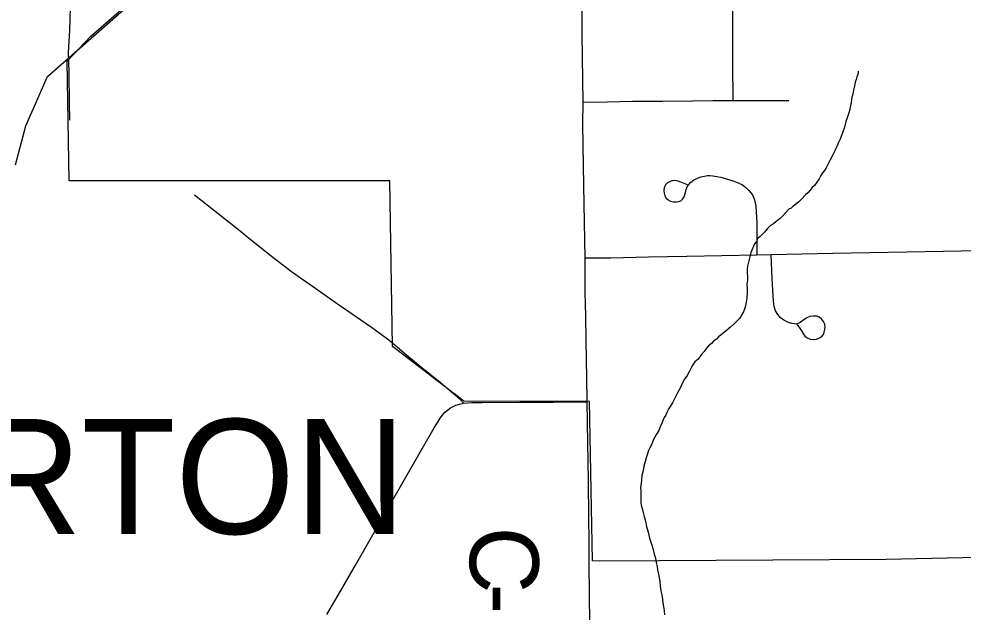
# Model space of a CAD drawing. Extents: x 103424 to 290657, y 38711 to 110967.
# Drawn here: x 156701 to 160839, y 57927 to 60525 of the extents above; entities that cross this region are included whole.
import ezdxf

# ---------------------------------------------------------------- set-up
doc = ezdxf.new("R2010")
doc.units = 0
for name, color, linetype in [('GM_X_City_Street', 7, 'Continuous'), ('GM_X_Corporation', 7, 'Continuous'), ('GM_X_Corporation_Text', 7, 'Continuous'), ('GM_X_County_Road', 7, 'Continuous'), ('GM_X_County_Road_Text', 7, 'Continuous'), ('GM_X_Minor_River', 7, 'Continuous'), ('GM_X_Rail_Line', 7, 'Continuous'), ('GM_X_Township_Road', 7, 'Continuous')]:
    doc.layers.add(name, color=color, linetype=linetype)

msp = doc.modelspace()

# ---------------------------------------------------------------- linework, layer by layer
at = {"layer": 'GM_X_City_Street'}
for points in [[(159182.5, 59478.1), (159178.7, 59713.4), (159176, 59881.9), (159173.1, 60063.8), (159173.8, 60160), (159169.7, 60457), (159169.7, 60880.9)], [(159831.2, 60168.2), (159830.6, 60333.3), (159830, 60498.3), (159829.3, 60663.4), (159828.9, 60773.7), (159828.5, 60884)], [(159173.8, 60160), (159281.4, 60162), (159391.2, 60165), (159522, 60165.6), (159652.8, 60166.2), (159742, 60167.2), (159831.2, 60168.2), (159963, 60167.3), (160076.3, 60168.2)], [(159631, 59798), (159602, 59810.6), (159590.5, 59814.7), (159576.3, 59816.9), (159564.7, 59816.2), (159555.1, 59813.6), (159544.3, 59806.9), (159535.7, 59798), (159529.8, 59787.2), (159527.9, 59774.1), (159529.8, 59761.8), (159532.7, 59751), (159538.3, 59740.6), (159546.5, 59732.8), (159557.7, 59726.8), (159570, 59724.2), (159583.4, 59723.9), (159593.4, 59725.7), (159602.4, 59728.7), (159609.8, 59735.4), (159615, 59742.8), (159619.1, 59751.8), (159622.5, 59764.8), (159625.1, 59777.9), (159629.6, 59790.1), (159637, 59800.6), (159645.9, 59810.1), (159657.5, 59818.4), (159672.8, 59825.9), (159690.7, 59833), (159705.9, 59837.1), (159718.6, 59838.9), (159729, 59839.7), (159742.3, 59838.3), (159776.9, 59832.1), (159831.1, 59815.8), (159853.4, 59807), (159872.6, 59797.9), (159887.7, 59786.8), (159900.6, 59773.9), (159915.8, 59754.1), (159925.8, 59732.1), (159930.7, 59705.8), (159933.1, 59678.2), (159934.8, 59635.7), (159935.9, 59492.2)], [(159182.5, 59478.1), (159295.2, 59479.4), (159460.2, 59483), (159544.6, 59484.9), (159629.1, 59486.7), (159782.5, 59489.5), (159935.9, 59492.2), (159997.9, 59492.9), (160132.9, 59496.2), (160267.9, 59499.6), (160430.5, 59502.7), (160593.2, 59505.7), (160751.8, 59508.6), (160910.5, 59511.5), (161075.5, 59514.2), (161212.7, 59516.4), (161349.9, 59518.6), (161514.9, 59521.3), (161649.9, 59523.5), (161736.1, 59524.9), (161784.8, 59525.7)], [(159191.8, 58847.5), (159190.8, 58952.1), (159187.6, 59117.2), (159185.6, 59223), (159183.5, 59328.9), (159182.5, 59478.1)], [(160112.4, 59186.3), (160131.4, 59158.8), (160145.5, 59135.9), (160156.3, 59127.8), (160168.7, 59122), (160182.8, 59120.4), (160197.1, 59122), (160207.7, 59126.3), (160218.5, 59132.7), (160227.1, 59143.1), (160230.9, 59152.5), (160233.4, 59164.3), (160234.3, 59175), (160232.7, 59187.8), (160227.8, 59200.1), (160219.3, 59210.9), (160209.1, 59218.7), (160196.9, 59222.8), (160182.6, 59224), (160168.2, 59221.7), (160154.5, 59215.7), (160135.4, 59202.7), (160125, 59195.2), (160116.8, 59191.2), (160109.8, 59188.9), (160088.9, 59190.8), (160074, 59195.6), (160054.1, 59205.4), (160039.6, 59216.7), (160027, 59230.6), (160017.1, 59246.5), (160011.1, 59265.7), (160007.8, 59288.9), (160002.5, 59386.9), (159997.9, 59492.9)]]:
    msp.add_lwpolyline(points, dxfattribs=at)
at = {"layer": 'GM_X_Corporation'}
msp.add_lwpolyline([(161771.2, 58184.7), (160501.7, 58157), (159508.2, 58151.7), (159244.9, 58150.4), (159215, 58151.6), (159202.5, 58850.2), (158651.2, 58850.7), (158338.2, 59090.8), (158326.5, 59816.1), (156921.7, 59816.4), (156912.5, 60339.8), (157016.4, 60449), (157152.1, 60568.5)], dxfattribs=at)
at = {"layer": 'GM_X_County_Road'}
for points in [[(159201.1, 58147.4), (159200.4, 58242.8), (159199.6, 58338.1), (159197.1, 58503.1), (159194.5, 58668.2), (159193.2, 58757.8), (159191.8, 58847.5)], [(159203.9, 57889.6), (159202.6, 57994.4), (159201.1, 58147.4)]]:
    msp.add_lwpolyline(points, dxfattribs=at)
at = {"layer": 'GM_X_Minor_River'}
for points in [[(160379.8, 60296.4), (160380, 60286.3), (160374.2, 60272), (160370.5, 60259.9), (160366.7, 60247.7), (160363, 60231.4), (160359.3, 60213.2), (160355.7, 60194.9), (160351.9, 60182.7), (160350.1, 60170.6), (160348.4, 60158.4), (160344.7, 60138.1), (160341.1, 60121.9), (160335.3, 60105.6), (160331.6, 60091.4), (160325.9, 60075.2), (160322.1, 60060.9), (160318.4, 60046.7), (160312.7, 60030.4), (160307, 60014.2), (160301.3, 59997.9), (160293.5, 59983.6), (160287.7, 59969.3), (160281.9, 59957.1), (160276.1, 59944.8), (160268.3, 59930.5), (160256.7, 59908.1), (160247, 59887.7), (160239.2, 59873.4), (160231.4, 59861.1), (160223.5, 59850.8), (160213.7, 59836.5), (160207.9, 59824.2), (160198.1, 59809.9), (160188.3, 59795.5), (160176.4, 59785.2), (160168.6, 59774.9), (160160.7, 59764.7), (160148.8, 59754.3), (160131, 59735.8), (160119.1, 59723.4), (160105.2, 59713), (160095.3, 59704.7), (160085.3, 59696.4), (160075.3, 59692.1), (160061.5, 59675.7), (160049.7, 59663.3), (160035.8, 59648.9), (160019.9, 59638.5), (160008, 59628.1), (159996, 59619.8), (159982.1, 59607.3), (159968.3, 59590.9), (159958.5, 59580.6), (159948.6, 59570.3), (159938.6, 59564), (159934.8, 59551.8), (159925, 59539.5), (159909.6, 59502.8), (159904, 59482.5), (159898.4, 59460.1), (159894.7, 59441.9), (159893, 59427.7), (159894, 59381.3), (159892.3, 59363.1), (159892.7, 59344.9), (159893.1, 59326.8), (159891.6, 59302.5), (159888, 59284.3), (159886.3, 59268.1), (159882.5, 59257.9), (159876.8, 59241.6), (159867, 59225.3), (159859.2, 59213), (159845.3, 59198.5), (159833.5, 59186.2), (159819.5, 59175.8), (159801.7, 59159.2), (159787.8, 59148.8), (159777.8, 59140.5), (159767.9, 59132.2), (159758, 59121.9), (159746.1, 59113.6), (159736.2, 59103.3), (159724.3, 59092.9), (159714.4, 59082.6), (159704.6, 59068.3), (159690.8, 59053.8), (159679, 59035.4), (159663.1, 59023), (159655.3, 59010.7), (159647.5, 58996.4), (159639.7, 58982.1), (159630, 58963.7), (159618.2, 58947.3), (159608.5, 58928.9), (159598.9, 58908.5), (159587.2, 58888.1), (159577.5, 58867.7), (159565.9, 58843.2), (159550.3, 58818.6)], [(159550.3, 58818.6), (159542.5, 58804.3), (159536.7, 58790.1), (159528.9, 58779.8), (159525, 58769.6), (159521.2, 58757.4), (159513.5, 58741.1), (159505.8, 58722.7), (159496.1, 58706.4), (159490.2, 58696.2), (159484.4, 58685.9), (159472.8, 58657.4), (159467, 58647.2), (159461.2, 58635), (159455.5, 58616.7), (159449.8, 58602.4), (159446.1, 58586.2), (159440.4, 58565.9), (159436.8, 58547.6), (159431.2, 58525.3), (159429.6, 58507.1), (159427.9, 58490.9), (159426.2, 58474.7), (159426.6, 58456.5), (159426.9, 58440.4), (159427.3, 58422.2), (159427.7, 58406.1), (159430, 58390), (159434.4, 58375.9), (159436.7, 58363.9), (159441.1, 58345.8), (159447.6, 58325.8), (159452.1, 58301.6), (159458.7, 58277.5), (159465.3, 58251.4), (159474, 58225.4), (159480.5, 58201.3), (159485, 58181.2), (159491.5, 58163.2), (159493.9, 58145), (159498.3, 58127), (159500.7, 58110.9), (159505.1, 58092.8), (159507.5, 58076.7), (159509.8, 58060.6), (159512.3, 58040.5), (159514.7, 58020.3), (159519.1, 58002.2), (159521.5, 57984.1), (159523.9, 57968), (159526.3, 57951.9), (159528.7, 57933.8), (159531.1, 57915.7)]]:
    msp.add_lwpolyline(points, dxfattribs=at)
at = {"layer": 'GM_X_Rail_Line'}
msp.add_lwpolyline([(156685.9, 59886.4), (156731.6, 60056.7), (156827.1, 60272.6), (158961.1, 62145.8), (159164.6, 62415.7), (159376.3, 62752.1), (159604.7, 63009.7), (159911.9, 63184.1), (160152.8, 63238.1), (160415.4, 63267.2), (161709.6, 63308.7)], dxfattribs=at)
at = {"layer": 'GM_X_Township_Road'}
for points in [[(156919.9, 60337.6), (156918.6, 60376.3), (156924.7, 60475.5), (156927.7, 60574.4), (156921.6, 60725.4), (156914, 60842.5)], [(156925, 60081.5), (156923.5, 60155.5), (156921.6, 60287.9), (156919.9, 60337.6)], [(157699.1, 59572.6), (157678.3, 59589.2), (157574.7, 59671.5), (157471.2, 59753.9)], [(158098.4, 59276.4), (158003.4, 59342.7), (157895.4, 59417.9), (157807.4, 59486.4), (157699.1, 59572.6)], [(158339, 59105), (158317.4, 59122.3), (158246.8, 59173.1), (158111.4, 59267.4), (158098.4, 59276.4)], [(158649.7, 58841.9), (158633.1, 58860.3), (158541, 58938.6), (158469.3, 58996.1), (158401.5, 59050.5), (158339, 59105)], [(158649.7, 58841.9), (158668.4, 58844), (158687.1, 58845.3), (158731.4, 58845.8), (158896.5, 58846.4), (159044.1, 58846.9), (159191.8, 58847.5)], [(158051.5, 57916.3), (158111, 58019.1), (158170.6, 58122), (158252.8, 58265.1), (158335, 58408.3), (158392, 58507.4), (158448.9, 58606.6), (158521.7, 58734.8), (158533.9, 58755.4), (158547.5, 58777.1), (158557.4, 58790.3), (158567.3, 58801.3), (158579.5, 58811.6), (158593.2, 58821.8), (158604.4, 58827.5), (158615.9, 58833.4), (158631.9, 58837.9), (158649.7, 58841.9)]]:
    msp.add_lwpolyline(points, dxfattribs=at)

# ---------------------------------------------------------------- texts
at = {"layer": 'GM_X_Corporation_Text'}
msp.add_text('BURTON', height=503.12, rotation=0, dxfattribs=at).set_placement((155556.1, 58269.6))
at = {"layer": 'GM_X_County_Road_Text'}
for s, rotation, p in [('C', 270.0234, (158677.4, 58301.2)), ('-', 270.2165, (158677.5, 58052.2))]:
    msp.add_text(s, height=301.9, rotation=rotation, dxfattribs=at).set_placement(p)

doc.saveas('drawing.dxf')
